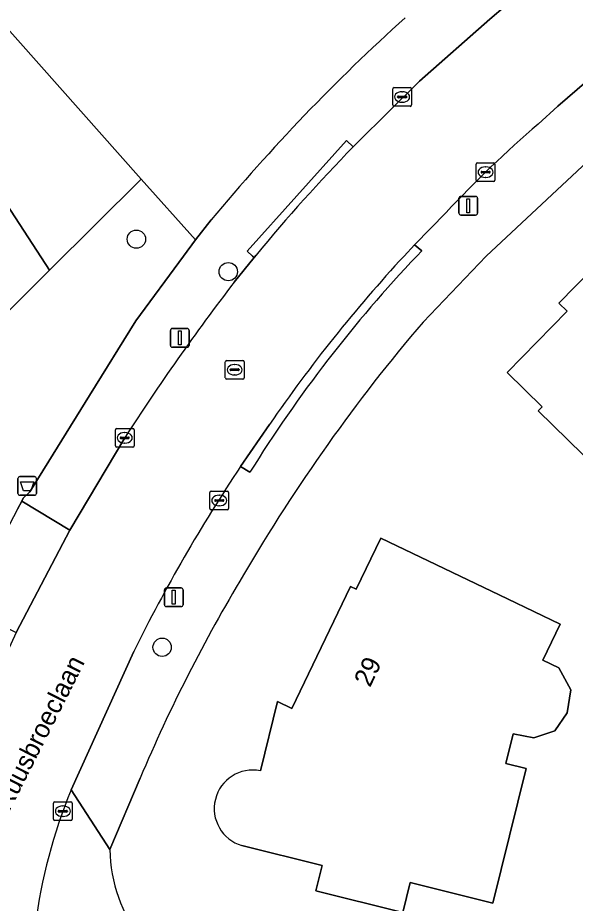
# Model space of a CAD drawing. Extents: x 161347 to 161881, y 382161 to 382804.
# Drawn here: x 161409.68 to 161439.43, y 382215.45 to 382262.72 of the extents above; entities that cross this region are included whole.
import ezdxf

# ---------------------------------------------------------------- set-up
doc = ezdxf.new("R2010")
doc.units = 0
for name, color, linetype in [('IMGEO_Afvalbak', 7, 'Continuous'), ('IMGEO_Boom', 7, 'Continuous'), ('IMGEO_Erf', 7, 'Continuous'), ('IMGEO_Groenvoorziening', 7, 'Continuous'), ('IMGEO_Kolk', 7, 'Continuous'), ('IMGEO_Lichtmast', 7, 'Continuous'), ('IMGEO_Openbare_ruimte_label', 7, 'Continuous'), ('IMGEO_Pand', 7, 'Continuous'), ('IMGEO_Pand_nummerreeks', 7, 'Continuous'), ('IMGEO_Rijbaan_lokaal_open', 7, 'Continuous'), ('IMGEO_Rioolput', 7, 'Continuous'), ('IMGEO_Voetpad_open', 7, 'Continuous')]:
    doc.layers.add(name, color=color, linetype=linetype)

msp = doc.modelspace()

# ---------------------------------------------------------------- linework, layer by layer
at = {"layer": 'IMGEO_Afvalbak'}
for p, q in [((161409.688, 382237.329), (161409.688, 382238.129)), ((161409.688, 382238.129), (161409.688, 382237.329)), ((161409.788, 382238.229), (161410.578, 382238.229)), ((161410.578, 382238.229), (161409.788, 382238.229)), ((161410.678, 382238.129), (161410.678, 382237.329)), ((161410.678, 382237.329), (161410.678, 382238.129)), ((161410.578, 382237.229), (161409.788, 382237.229)), ((161409.788, 382237.229), (161410.578, 382237.229))]:
    msp.add_line(p, q, dxfattribs=at)
msp.add_lwpolyline([(161409.831, 382237.943), (161410.535, 382237.943), (161410.386, 382237.473), (161409.98, 382237.473), (161409.831, 382237.943)], dxfattribs=at)
for centre, start, end in [((161409.788, 382238.129), 90, 180), ((161409.788, 382238.129), 90, 180), ((161410.578, 382238.129), 0, 90), ((161410.578, 382238.129), 360, 90), ((161409.788, 382237.329), 180, 270), ((161409.788, 382237.329), 180, 270), ((161410.578, 382237.329), 270, 0), ((161410.578, 382237.329), 270, 0)]:
    msp.add_arc(centre, 0.1, start, end, dxfattribs=at)
at = {"layer": 'IMGEO_Boom'}
for centre in [(161416.011, 382250.899), (161420.911, 382249.164), (161417.385, 382229.117)]:
    msp.add_circle(centre, 0.489, dxfattribs=at)
at = {"layer": 'IMGEO_Erf'}
for points in [[(161441.023, 382284.25), (161435.438, 382291.085), (161438.742, 382293.784), (161435.911, 382297.247), (161438.146, 382299.071), (161432.164, 382306.393), (161410.698, 382290.675), (161402.221, 382283.95), (161405.506, 382280.209), (161406.184, 382279.438), (161405.767, 382279.072), (161406.734, 382277.971), (161407.448, 382277.158), (161401.225, 382271.81), (161400.57, 382272.555), (161400.157, 382272.252), (161400.981, 382271.324), (161416.272, 382254.11), (161419.161, 382250.858), (161420.005, 382251.925)], [(161515.43, 382277.538), (161511.368, 382280.308), (161507.38, 382283.438), (161503.628, 382286.721), (161500, 382290.141), (161496.366, 382293.828), (161493.141, 382297.37), (161489.742, 382297.254), (161478.663, 382288.406), (161466.13, 382277.891), (161441.144, 382256.043), (161434.673, 382250), (161431.306, 382246.471)], [(161442.21, 382237.067), (161437.441, 382241.734), (161437.657, 382241.954), (161435.79, 382243.781), (161438.994, 382247.056), (161438.55, 382247.491), (161440.343, 382249.322)], [(161422.628, 382222.521), (161423.548, 382226.218), (161424.312, 382225.85), (161427.444, 382232.357), (161427.731, 382232.219), (161429.046, 382234.948), (161435.805, 382231.694), (161438.615, 382230.342), (161437.691, 382228.423), (161438.547, 382228.011), (161439.188, 382226.852), (161438.998, 382225.624), (161438.34, 382224.661), (161437.219, 382224.274), (161436.111, 382224.5), (161435.717, 382222.918), (161436.812, 382222.644), (161435.026, 382215.462)], [(161416.21, 382222.125), (161414.589, 382218.315)], [(161435.026, 382215.462), (161430.616, 382216.559), (161430.219, 382214.962), (161425.58, 382216.116), (161425.917, 382217.468), (161421.642, 382218.531)]]:
    msp.add_lwpolyline(points, dxfattribs=at)
for centre, radius, start, end in [((161498.813, 382186.718), 102.287, 132.0104, 140.39531), ((161502.432, 382185.846), 93.458, 139.55691, 149.7147), ((161495.014, 382188.877), 85.531, 148.96217, 157.1248), ((161422.22, 382220.505), 2.057, 78.5567, 253.6819), ((161422.737, 382218.488), 8.15, 181.2145, 253.1763)]:
    msp.add_arc(centre, radius, start, end, dxfattribs=at)
at = {"layer": 'IMGEO_Groenvoorziening'}
for points in [[(161416.272, 382254.11), (161400.981, 382271.324), (161400.981, 382266.785), (161400.981, 382265.217), (161411.38, 382249.236)], [(161411.38, 382249.236), (161400.981, 382265.217), (161397.405, 382263.726), (161398.282, 382261.318), (161400.606, 382256.246), (161406.575, 382244.448)]]:
    msp.add_lwpolyline(points, close=True, dxfattribs=at)
msp.add_lwpolyline([(161409.667, 382236.489), (161409.889, 382236.909), (161409.971, 382237.072), (161410.319, 382237.414), (161413.512, 382242.562), (161415.977, 382246.535), (161418.529, 382250), (161419.161, 382250.858), (161416.272, 382254.11), (161411.38, 382249.236), (161406.575, 382244.448), (161404.802, 382242.987), (161407.145, 382238.181)], dxfattribs=at)
at = {"layer": 'IMGEO_Kolk'}
for p, q in [((161429.69, 382258.064), (161429.69, 382258.916)), ((161429.765, 382258.99), (161430.617, 382258.99)), ((161430.691, 382258.916), (161430.691, 382258.064)), ((161429.949, 382258.484), (161429.949, 382258.496)), ((161430.387, 382258.447), (161429.989, 382258.447)), ((161429.992, 382258.533), (161430.39, 382258.533)), ((161430.178, 382258.77), (161430.203, 382258.77)), ((161430.433, 382258.496), (161430.433, 382258.484)), ((161430.617, 382257.99), (161429.765, 382257.99)), ((161430.201, 382258.21), (161430.176, 382258.21)), ((161434.143, 382254.05), (161434.143, 382254.902)), ((161434.218, 382254.976), (161435.07, 382254.976)), ((161434.631, 382254.756), (161434.656, 382254.756)), ((161435.144, 382254.902), (161435.144, 382254.05)), ((161434.402, 382254.47), (161434.402, 382254.482)), ((161434.84, 382254.433), (161434.442, 382254.433)), ((161434.445, 382254.519), (161434.843, 382254.519)), ((161434.654, 382254.196), (161434.629, 382254.196)), ((161434.886, 382254.482), (161434.886, 382254.47)), ((161435.07, 382253.976), (161434.218, 382253.976)), ((161414.888, 382239.867), (161414.888, 382240.719)), ((161414.963, 382240.793), (161415.815, 382240.793)), ((161415.376, 382240.573), (161415.401, 382240.573)), ((161415.889, 382240.719), (161415.889, 382239.867)), ((161415.147, 382240.287), (161415.147, 382240.299)), ((161415.585, 382240.25), (161415.187, 382240.25)), ((161415.19, 382240.336), (161415.588, 382240.336)), ((161415.399, 382240.013), (161415.374, 382240.013)), ((161415.631, 382240.299), (161415.631, 382240.287)), ((161415.815, 382239.793), (161414.963, 382239.793)), ((161419.93, 382236.523), (161419.93, 382237.375)), ((161420.005, 382237.449), (161420.857, 382237.449)), ((161420.418, 382237.229), (161420.443, 382237.229)), ((161420.931, 382237.375), (161420.931, 382236.523)), ((161420.189, 382236.943), (161420.189, 382236.955)), ((161420.627, 382236.906), (161420.229, 382236.906)), ((161420.232, 382236.992), (161420.63, 382236.992)), ((161420.441, 382236.669), (161420.416, 382236.669)), ((161420.673, 382236.955), (161420.673, 382236.943)), ((161420.857, 382236.449), (161420.005, 382236.449)), ((161411.585, 382219.938), (161411.585, 382220.79)), ((161411.66, 382220.864), (161412.512, 382220.864)), ((161412.073, 382220.644), (161412.098, 382220.644)), ((161412.586, 382220.79), (161412.586, 382219.938)), ((161411.844, 382220.358), (161411.844, 382220.37)), ((161412.282, 382220.321), (161411.884, 382220.321)), ((161411.887, 382220.407), (161412.285, 382220.407)), ((161412.096, 382220.084), (161412.071, 382220.084)), ((161412.328, 382220.37), (161412.328, 382220.358)), ((161412.512, 382219.864), (161411.66, 382219.864))]:
    msp.add_line(p, q, dxfattribs=at)
for points in [[(161429.69, 382258.064), (161429.69, 382258.916)], [(161429.765, 382258.99), (161430.617, 382258.99)], [(161430.691, 382258.916), (161430.691, 382258.064)], [(161430.617, 382257.99), (161429.765, 382257.99)], [(161434.143, 382254.05), (161434.143, 382254.902)], [(161434.218, 382254.976), (161435.07, 382254.976)], [(161435.144, 382254.902), (161435.144, 382254.05)], [(161435.07, 382253.976), (161434.218, 382253.976)], [(161414.888, 382239.867), (161414.888, 382240.719)], [(161414.963, 382240.793), (161415.815, 382240.793)], [(161415.889, 382240.719), (161415.889, 382239.867)], [(161415.815, 382239.793), (161414.963, 382239.793)], [(161419.93, 382236.523), (161419.93, 382237.375)], [(161420.005, 382237.449), (161420.857, 382237.449)], [(161420.931, 382237.375), (161420.931, 382236.523)], [(161420.857, 382236.449), (161420.005, 382236.449)], [(161411.585, 382219.938), (161411.585, 382220.79)], [(161411.66, 382220.864), (161412.512, 382220.864)], [(161412.586, 382220.79), (161412.586, 382219.938)], [(161412.512, 382219.864), (161411.66, 382219.864)]]:
    msp.add_lwpolyline(points, dxfattribs=at)
for centre, radius, start, end in [((161429.767, 382258.914), 0.0765, 91.552, 178.448), ((161429.767, 382258.914), 0.0765, 91.552, 178.448), ((161430.615, 382258.914), 0.0765, 1.552, 88.448), ((161430.615, 382258.914), 0.0765, 1.552, 88.448), ((161429.989, 382258.493), 0.0403, 85.8775, 175.7526), ((161429.986, 382258.483), 0.0366, 178.938, 274.7102), ((161430.39, 382258.49), 0.043, 264.8664, 352.4533), ((161430.394, 382258.495), 0.0386, 1.7309, 96.639), ((161429.767, 382258.066), 0.0765, 181.552, 268.448), ((161429.767, 382258.066), 0.0765, 181.552, 268.448), ((161430.615, 382258.066), 0.0765, 271.552, 358.448), ((161430.615, 382258.066), 0.0765, 271.552, 358.448), ((161434.22, 382254.9), 0.0765, 91.552, 178.448), ((161434.22, 382254.9), 0.0765, 91.552, 178.448), ((161435.068, 382254.9), 0.0765, 1.552, 88.448), ((161435.068, 382254.9), 0.0765, 1.552, 88.448), ((161434.442, 382254.479), 0.0403, 85.8775, 175.7526), ((161434.439, 382254.469), 0.0366, 178.938, 274.7102), ((161434.843, 382254.476), 0.043, 264.8664, 352.4533), ((161434.847, 382254.481), 0.0386, 1.7309, 96.639), ((161434.22, 382254.052), 0.0765, 181.552, 268.448), ((161434.22, 382254.052), 0.0765, 181.552, 268.448), ((161435.068, 382254.052), 0.0765, 271.552, 358.448), ((161435.068, 382254.052), 0.0765, 271.552, 358.448), ((161414.965, 382240.717), 0.0765, 91.552, 178.448), ((161414.965, 382240.717), 0.0765, 91.552, 178.448), ((161415.813, 382240.717), 0.0765, 1.552, 88.448), ((161415.813, 382240.717), 0.0765, 1.552, 88.448), ((161415.187, 382240.296), 0.0403, 85.8775, 175.7526), ((161415.184, 382240.286), 0.0366, 178.938, 274.7102), ((161415.588, 382240.293), 0.043, 264.8664, 352.4533), ((161415.592, 382240.298), 0.0386, 1.7309, 96.639), ((161414.965, 382239.869), 0.0765, 181.552, 268.448), ((161414.965, 382239.869), 0.0765, 181.552, 268.448), ((161415.813, 382239.869), 0.0765, 271.552, 358.448), ((161415.813, 382239.869), 0.0765, 271.552, 358.448), ((161420.007, 382237.373), 0.0765, 91.552, 178.448), ((161420.007, 382237.373), 0.0765, 91.552, 178.448), ((161420.855, 382237.373), 0.0765, 1.552, 88.448), ((161420.855, 382237.373), 0.0765, 1.552, 88.448), ((161420.229, 382236.952), 0.0403, 85.8775, 175.7526), ((161420.226, 382236.942), 0.0366, 178.938, 274.7102), ((161420.63, 382236.949), 0.043, 264.8664, 352.4533), ((161420.634, 382236.954), 0.0386, 1.7309, 96.639), ((161420.007, 382236.525), 0.0765, 181.552, 268.448), ((161420.007, 382236.525), 0.0765, 181.552, 268.448), ((161420.855, 382236.525), 0.0765, 271.552, 358.448), ((161420.855, 382236.525), 0.0765, 271.552, 358.448), ((161411.662, 382220.788), 0.0765, 91.552, 178.448), ((161411.662, 382220.788), 0.0765, 91.552, 178.448), ((161412.51, 382220.788), 0.0765, 1.552, 88.448), ((161412.51, 382220.788), 0.0765, 1.552, 88.448), ((161411.884, 382220.367), 0.0403, 85.8775, 175.7526), ((161411.881, 382220.357), 0.0366, 178.938, 274.7102), ((161412.285, 382220.364), 0.043, 264.8664, 352.4533), ((161412.289, 382220.369), 0.0386, 1.7309, 96.639), ((161411.662, 382219.94), 0.0765, 181.552, 268.448), ((161411.662, 382219.94), 0.0765, 181.552, 268.448), ((161412.51, 382219.94), 0.0765, 271.552, 358.448), ((161412.51, 382219.94), 0.0765, 271.552, 358.448)]:
    msp.add_arc(centre, radius, start, end, dxfattribs=at)
for centre, major_axis, ratio, start_param, end_param in [((161430.177, 382258.49), (-0.387, 0.002), 0.722429, 4.712389, 7.853982), ((161430.202, 382258.49), (-0.39, 0.002), 0.717154, 1.570796, 4.712389), ((161434.63, 382254.476), (-0.387, 0.002), 0.722429, 4.712389, 7.853982), ((161434.655, 382254.476), (-0.39, 0.002), 0.717154, 1.570796, 4.712389), ((161415.375, 382240.293), (-0.387, 0.002), 0.722429, 4.712389, 7.853982), ((161415.4, 382240.293), (-0.39, 0.002), 0.717154, 1.570796, 4.712389), ((161420.417, 382236.949), (-0.387, 0.002), 0.722429, 4.712389, 7.853982), ((161420.442, 382236.949), (-0.39, 0.002), 0.717154, 1.570796, 4.712389), ((161412.072, 382220.364), (-0.387, 0.002), 0.722429, 4.712389, 7.853982), ((161412.097, 382220.364), (-0.39, 0.002), 0.717154, 1.570796, 4.712389)]:
    msp.add_ellipse(centre, major_axis=major_axis, ratio=ratio, start_param=start_param, end_param=end_param, dxfattribs=at)
at = {"layer": 'IMGEO_Lichtmast'}
for p, q in [((161433.324, 382253.185), (161434.114, 382253.185)), ((161434.114, 382253.185), (161433.324, 382253.185)), ((161433.224, 382252.285), (161433.224, 382253.085)), ((161433.224, 382253.085), (161433.224, 382252.285)), ((161434.214, 382253.085), (161434.214, 382252.285)), ((161434.214, 382252.285), (161434.214, 382253.085)), ((161434.114, 382252.185), (161433.324, 382252.185)), ((161433.324, 382252.185), (161434.114, 382252.185)), ((161417.83, 382245.23), (161417.83, 382246.03)), ((161417.83, 382246.03), (161417.83, 382245.23)), ((161417.93, 382246.13), (161418.72, 382246.13)), ((161418.72, 382246.13), (161417.93, 382246.13)), ((161418.82, 382246.03), (161418.82, 382245.23)), ((161418.82, 382245.23), (161418.82, 382246.03)), ((161418.72, 382245.13), (161417.93, 382245.13)), ((161417.93, 382245.13), (161418.72, 382245.13)), ((161417.508, 382231.383), (161417.508, 382232.183)), ((161417.508, 382232.183), (161417.508, 382231.383)), ((161417.608, 382232.283), (161418.398, 382232.283)), ((161418.398, 382232.283), (161417.608, 382232.283)), ((161418.498, 382232.183), (161418.498, 382231.383)), ((161418.498, 382231.383), (161418.498, 382232.183)), ((161418.398, 382231.283), (161417.608, 382231.283)), ((161417.608, 382231.283), (161418.398, 382231.283))]:
    msp.add_line(p, q, dxfattribs=at)
for points in [[(161433.644, 382253.06), (161433.794, 382253.06), (161433.794, 382252.31), (161433.644, 382252.31), (161433.644, 382253.06)], [(161418.25, 382246.005), (161418.4, 382246.005), (161418.4, 382245.255), (161418.25, 382245.255), (161418.25, 382246.005)], [(161417.928, 382232.158), (161418.078, 382232.158), (161418.078, 382231.408), (161417.928, 382231.408), (161417.928, 382232.158)]]:
    msp.add_lwpolyline(points, dxfattribs=at)
for centre, start, end in [((161433.324, 382253.085), 90, 180), ((161433.324, 382253.085), 90, 180), ((161434.114, 382253.085), 0, 90), ((161434.114, 382253.085), 360, 90), ((161433.324, 382252.285), 180, 270), ((161433.324, 382252.285), 180, 270), ((161434.114, 382252.285), 270, 0), ((161434.114, 382252.285), 270, 0), ((161417.93, 382246.03), 90, 180), ((161417.93, 382246.03), 90, 180), ((161418.72, 382246.03), 0, 90), ((161418.72, 382246.03), 360, 90), ((161417.93, 382245.23), 180, 270), ((161417.93, 382245.23), 180, 270), ((161418.72, 382245.23), 270, 0), ((161418.72, 382245.23), 270, 0), ((161417.608, 382232.183), 90, 180), ((161417.608, 382232.183), 90, 180), ((161418.398, 382232.183), 0, 90), ((161418.398, 382232.183), 360, 90), ((161417.608, 382231.383), 180, 270), ((161417.608, 382231.383), 180, 270), ((161418.398, 382231.383), 270, 0), ((161418.398, 382231.383), 270, 0)]:
    msp.add_arc(centre, 0.1, start, end, dxfattribs=at)
at = {"layer": 'IMGEO_Pand'}
msp.add_lwpolyline([(161442.119, 382232.914), (161446.641, 382229.335), (161448.936, 382229.455), (161448.963, 382231.58), (161445.96, 382234.517), (161448.03, 382236.632), (161446.864, 382237.771), (161449.8, 382240.772), (161441.188, 382249.2), (161440.835, 382248.84), (161440.343, 382249.322), (161438.55, 382247.491), (161438.994, 382247.056), (161435.79, 382243.781), (161437.657, 382241.954), (161437.441, 382241.734), (161442.21, 382237.067), (161439.89, 382234.697)], close=True, dxfattribs=at)
msp.add_lwpolyline([(161421.642, 382218.531), (161425.917, 382217.468), (161425.58, 382216.116), (161430.219, 382214.962), (161430.616, 382216.559), (161435.026, 382215.462), (161436.812, 382222.644), (161435.717, 382222.918), (161436.111, 382224.5), (161437.219, 382224.274), (161438.34, 382224.661), (161438.998, 382225.624), (161439.188, 382226.852), (161438.547, 382228.011), (161437.691, 382228.423), (161438.615, 382230.342), (161435.805, 382231.694), (161429.046, 382234.948), (161427.731, 382232.219), (161427.444, 382232.357), (161424.312, 382225.85), (161423.548, 382226.218), (161422.628, 382222.521)], dxfattribs=at)
msp.add_arc((161422.22, 382220.505), 2.057, 78.5567, 253.6819, dxfattribs=at)
at = {"layer": 'IMGEO_Rijbaan_lokaal_open'}
for points in [[(161484.17, 382304.313), (161483.217, 382303.577), (161475.956, 382297.831), (161470.542, 382293.47), (161465.943, 382289.653), (161465.442, 382289.231), (161464.389, 382288.356), (161457.668, 382282.547), (161453.746, 382279.09), (161448.666, 382274.709), (161447.285, 382273.5), (161444.034, 382270.665), (161436.549, 382264.08), (161434.865, 382262.644), (161431.117, 382259.326), (161427.809, 382256.063), (161427.585, 382255.834)], [(161437.449, 382257.041), (161438.498, 382257.995), (161445.33, 382263.909), (161451.744, 382269.472), (161455.325, 382272.559), (161467.155, 382282.783), (161474.03, 382288.594), (161486.884, 382298.805), (161488.639, 382300.196)], [(161430.295, 382250), (161430.846, 382250.59), (161432.54, 382252.33)], [(161422.4, 382250.051), (161422.294, 382249.922), (161421.227, 382248.599)], [(161421.57, 382238.767), (161423.12, 382241.014)], [(161415.388, 382240.289), (161412.464, 382235.372), (161409.598, 382229.896), (161407.884, 382226.209), (161407.034, 382224.05), (161405.195, 382219.447)], [(161412.536, 382221.514), (161415.87, 382228.895)]]:
    msp.add_lwpolyline(points, dxfattribs=at)
for centre, radius, start, end in [((161477.877, 382210.001), 62.026, 130.67683, 136.96496), ((161493.914, 382191.148), 92.649, 135.71847, 140.52314), ((161488.694, 382196.013), 79.53, 137.24812, 145.53965), ((161517.936, 382174.44), 121.87, 142.51818, 147.29443), ((161494.857, 382189.87), 88.101, 146.28893, 153.7076), ((161438.238, 382210.834), 27.833, 157.4355, 172.9124)]:
    msp.add_arc(centre, radius, start, end, dxfattribs=at)
at = {"layer": 'IMGEO_Rioolput'}
for p, q in [((161420.756, 382243.503), (161420.756, 382244.355)), ((161420.831, 382244.429), (161421.683, 382244.429)), ((161421.244, 382244.209), (161421.269, 382244.209)), ((161421.757, 382244.355), (161421.757, 382243.503)), ((161421.015, 382243.923), (161421.015, 382243.935)), ((161421.453, 382243.886), (161421.055, 382243.886)), ((161421.058, 382243.972), (161421.456, 382243.972)), ((161421.499, 382243.935), (161421.499, 382243.923)), ((161421.683, 382243.429), (161420.831, 382243.429)), ((161421.267, 382243.649), (161421.242, 382243.649))]:
    msp.add_line(p, q, dxfattribs=at)
for points in [[(161420.756, 382243.503), (161420.756, 382244.355)], [(161420.831, 382244.429), (161421.683, 382244.429)], [(161421.757, 382244.355), (161421.757, 382243.503)], [(161421.683, 382243.429), (161420.831, 382243.429)]]:
    msp.add_lwpolyline(points, dxfattribs=at)
for centre, radius, start, end in [((161420.833, 382244.353), 0.0765, 91.552, 178.448), ((161420.833, 382244.353), 0.0765, 91.552, 178.448), ((161421.681, 382244.353), 0.0765, 1.552, 88.448), ((161421.681, 382244.353), 0.0765, 1.552, 88.448), ((161421.055, 382243.932), 0.0403, 85.8775, 175.7526), ((161421.052, 382243.922), 0.0366, 178.938, 274.7102), ((161421.456, 382243.929), 0.043, 264.8664, 352.4533), ((161421.46, 382243.934), 0.0386, 1.7309, 96.639), ((161420.833, 382243.505), 0.0765, 181.552, 268.448), ((161420.833, 382243.505), 0.0765, 181.552, 268.448), ((161421.681, 382243.505), 0.0765, 271.552, 358.448), ((161421.681, 382243.505), 0.0765, 271.552, 358.448)]:
    msp.add_arc(centre, radius, start, end, dxfattribs=at)
for centre, major_axis, ratio, start_param, end_param in [((161421.243, 382243.929), (-0.387, 0.002), 0.722429, 4.712389, 7.853982), ((161421.268, 382243.929), (-0.39, 0.002), 0.717154, 1.570796, 4.712389)]:
    msp.add_ellipse(centre, major_axis=major_axis, ratio=ratio, start_param=start_param, end_param=end_param, dxfattribs=at)
at = {"layer": 'IMGEO_Voetpad_open'}
for points in [[(161488.639, 382300.196), (161486.884, 382298.805), (161474.03, 382288.594), (161467.155, 382282.783), (161455.325, 382272.559), (161451.744, 382269.472), (161452.071, 382269.095), (161445.657, 382263.532), (161445.33, 382263.909), (161438.498, 382257.995), (161437.449, 382257.041)], [(161431.306, 382246.471), (161434.673, 382250), (161441.144, 382256.043), (161466.13, 382277.891)], [(161421.227, 382248.599), (161422.294, 382249.922), (161422.207, 382250), (161421.922, 382250.255), (161427.213, 382256.167), (161427.585, 382255.834), (161427.809, 382256.063), (161431.117, 382259.326), (161434.865, 382262.644), (161436.549, 382264.08), (161444.034, 382270.665), (161443.706, 382271.041), (161446.957, 382273.876), (161447.285, 382273.5), (161448.666, 382274.709)], [(161427.585, 382255.834), (161427.213, 382256.167), (161421.922, 382250.255), (161422.207, 382250), (161422.294, 382249.922), (161422.4, 382250.051)], [(161432.54, 382252.33), (161430.846, 382250.59), (161431.235, 382250.277), (161430.972, 382250)], [(161420.005, 382251.925), (161419.161, 382250.858), (161418.529, 382250), (161415.977, 382246.535), (161413.512, 382242.562), (161410.319, 382237.414), (161409.971, 382237.072), (161409.889, 382236.909), (161412.464, 382235.372), (161415.388, 382240.289)], [(161430.972, 382250), (161431.235, 382250.277), (161430.846, 382250.59), (161430.295, 382250)], [(161423.12, 382241.014), (161421.57, 382238.767), (161422.067, 382238.456)], [(161422.067, 382238.456), (161421.57, 382238.767)], [(161415.87, 382228.895), (161412.536, 382221.514), (161414.589, 382218.315), (161416.21, 382222.125)], [(161414.589, 382218.315), (161412.536, 382221.514)]]:
    msp.add_lwpolyline(points, dxfattribs=at)
msp.add_lwpolyline([(161409.889, 382236.909), (161409.667, 382236.489), (161407.493, 382232.368), (161407.027, 382231.181), (161409.598, 382229.896), (161412.464, 382235.372)], close=True, dxfattribs=at)
for centre, radius, start, end in [((161498.813, 382186.718), 102.287, 132.0104, 140.39531), ((161477.877, 382210.001), 62.026, 130.67683, 136.96496), ((161493.914, 382191.148), 92.649, 135.71847, 140.52314), ((161483.289, 382200.436), 72.067, 136.54798, 148.15909), ((161483.289, 382200.436), 72.067, 136.54798, 148.15909), ((161488.694, 382196.013), 79.53, 137.24812, 145.53965), ((161517.936, 382174.44), 121.87, 142.51818, 147.29443), ((161502.432, 382185.846), 93.458, 139.55691, 149.7147), ((161494.857, 382189.87), 88.101, 146.28893, 153.7076), ((161495.014, 382188.877), 85.531, 148.96217, 157.1248), ((161438.238, 382210.834), 27.833, 157.4355, 172.9124), ((161422.737, 382218.488), 8.15, 181.2145, 253.1763)]:
    msp.add_arc(centre, radius, start, end, dxfattribs=at)

# ---------------------------------------------------------------- texts
at = {"layer": 'IMGEO_Openbare_ruimte_label'}
msp.add_text('Ruusbroeclaan', height=1, rotation=63.1786, dxfattribs=at).set_placement((161409.226, 382220.311))
at = {"layer": 'IMGEO_Pand_nummerreeks'}
msp.add_text('29', height=1, rotation=64.2972, dxfattribs=at).set_placement((161428.475, 382226.936))

doc.saveas('drawing.dxf')
